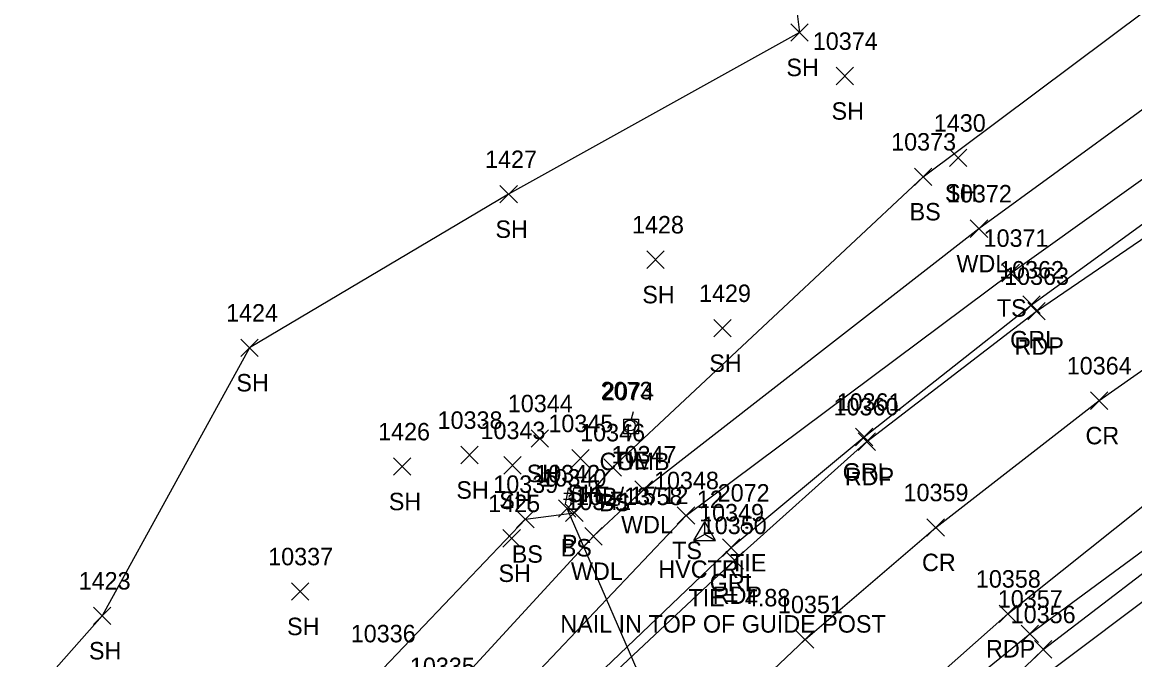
# Model space of a CAD drawing. Extents: x 1651685 to 1653558, y 889533 to 891085.
# Drawn here: x 1652813.1 to 1652940.5, y 890652 to 890725 of the extents above; entities that cross this region are included whole.
import ezdxf

# ---------------------------------------------------------------- set-up
doc = ezdxf.new("R2010")
doc.units = 0
for name, color, linetype in [('C_A', 7, 'Continuous'), ('C_C', 7, 'Continuous'), ('C_I', 7, 'Continuous'), ('CBP', 7, 'Continuous'), ('CPSM', 7, 'Continuous'), ('D_A', 7, 'Continuous'), ('D_I', 7, 'Continuous'), ('D_TIC', 7, 'Continuous'), ('DCP', 7, 'Continuous'), ('L_A', 7, 'Continuous'), ('L_I', 7, 'Continuous'), ('L_TIC', 7, 'Continuous'), ('LAWA', 7, 'Continuous'), ('LELB', 7, 'Continuous'), ('LSOGP', 7, 'Continuous'), ('P_A', 7, 'Continuous'), ('P_I', 7, 'Continuous'), ('P_TIC', 7, 'Continuous'), ('PET', 7, 'Continuous'), ('PRC', 7, 'Continuous'), ('R_A', 7, 'Continuous'), ('R_I', 7, 'Continuous'), ('R_TIC', 7, 'Continuous'), ('RGR', 7, 'Continuous'), ('U_A', 7, 'Continuous'), ('U_C', 7, 'Continuous'), ('U_I', 7, 'Continuous'), ('UP', 7, 'Continuous')]:
    doc.layers.add(name, color=color, linetype=linetype)

msp = doc.modelspace()

# ---------------------------------------------------------------- linework, layer by layer
at = {"layer": 'CBP'}
for centre, radius in [((1652882.68, 890678.86), 0.625), ((1652882.68, 890678.86), 0.0833), ((1652896.09, 890667.15), 0.625), ((1652896.09, 890667.15), 0.0833)]:
    msp.add_circle(centre, radius, dxfattribs=at)
at = {"layer": 'CPSM'}
for p, q in [((1652890.01, 890665.68), (1652891.26, 890667.85)), ((1652892.51, 890665.68), (1652891.26, 890667.85)), ((1652891.26, 890666.41), (1652891.26, 890667.85)), ((1652890.01, 890665.68), (1652891.26, 890666.41)), ((1652891.26, 890666.41), (1652891.26, 890666.41)), ((1652891.26, 890666.41), (1652892.51, 890665.68)), ((1652890.01, 890665.68), (1652892.51, 890665.68))]:
    msp.add_line(p, q, dxfattribs=at)
at = {"layer": 'D_TIC'}
for points in [[(1652874.51, 890668.35), (1652876.51, 890670.35)], [(1652876.51, 890668.35), (1652874.51, 890670.35)]]:
    msp.add_lwpolyline(points, dxfattribs=at)
at = {"layer": 'DCP'}
msp.add_lwpolyline([(1652896.07, 890622.05), (1652875.51, 890669.35)], dxfattribs=at)
at = {"layer": 'L_TIC'}
for points in [[(1652901.13, 890722.86), (1652903.13, 890724.86)], [(1652903.13, 890722.86), (1652901.13, 890724.86)], [(1652906.32, 890717.87), (1652908.32, 890719.87)], [(1652908.32, 890717.87), (1652906.32, 890719.87)], [(1652919.3, 890708.5), (1652921.3, 890710.5)], [(1652921.3, 890708.5), (1652919.3, 890710.5)], [(1652915.29, 890706.34), (1652917.29, 890708.34)], [(1652917.29, 890706.34), (1652915.29, 890708.34)], [(1652867.79, 890704.34), (1652869.79, 890706.34)], [(1652869.79, 890704.34), (1652867.79, 890706.34)], [(1652921.69, 890700.4), (1652923.69, 890702.4)], [(1652923.69, 890700.4), (1652921.69, 890702.4)], [(1652884.63, 890696.85), (1652886.63, 890698.85)], [(1652886.63, 890696.85), (1652884.63, 890698.85)], [(1652925.33, 890695.32), (1652927.33, 890697.32)], [(1652927.33, 890695.32), (1652925.33, 890697.32)], [(1652892.31, 890689), (1652894.31, 890691)], [(1652894.31, 890689), (1652892.31, 890691)], [(1652838.1, 890686.76), (1652840.1, 890688.76)], [(1652840.1, 890686.76), (1652838.1, 890688.76)], [(1652871.37, 890676.38), (1652873.37, 890678.38)], [(1652873.37, 890676.38), (1652871.37, 890678.38)], [(1652863.32, 890674.48), (1652865.32, 890676.48)], [(1652865.32, 890674.48), (1652863.32, 890676.48)], [(1652855.58, 890673.16), (1652857.58, 890675.16)], [(1652857.58, 890673.16), (1652855.58, 890675.16)], [(1652868.24, 890673.3), (1652870.24, 890675.3)], [(1652870.24, 890673.3), (1652868.24, 890675.3)], [(1652876.02, 890674.1), (1652878.02, 890676.1)], [(1652878.02, 890674.1), (1652876.02, 890676.1)], [(1652879.71, 890673.05), (1652881.71, 890675.05)], [(1652881.71, 890673.05), (1652879.71, 890675.05)], [(1652883.26, 890670.52), (1652885.26, 890672.52)], [(1652885.26, 890670.52), (1652883.26, 890672.52)], [(1652869.71, 890667.15), (1652871.71, 890669.15)], [(1652871.71, 890667.15), (1652869.71, 890669.15)], [(1652875.32, 890667.87), (1652877.32, 890669.87)], [(1652877.32, 890667.87), (1652875.32, 890669.87)], [(1652888.12, 890667.57), (1652890.12, 890669.57)], [(1652890.12, 890667.57), (1652888.12, 890669.57)], [(1652868.14, 890664.95), (1652870.14, 890666.95)], [(1652870.14, 890664.95), (1652868.14, 890666.95)], [(1652877.51, 890665.18), (1652879.51, 890667.18)], [(1652879.51, 890665.18), (1652877.51, 890667.18)], [(1652843.91, 890658.86), (1652845.91, 890660.86)], [(1652845.91, 890658.86), (1652843.91, 890660.86)], [(1652821.21, 890656.08), (1652823.21, 890658.08)], [(1652823.21, 890656.08), (1652821.21, 890658.08)], [(1652927.52, 890654.01), (1652929.52, 890656.01)], [(1652929.52, 890654.01), (1652927.52, 890656.01)], [(1652929.05, 890652.23), (1652931.05, 890654.23)], [(1652931.05, 890652.23), (1652929.05, 890654.23)]]:
    msp.add_lwpolyline(points, dxfattribs=at)
at = {"layer": 'LAWA'}
msp.add_lwpolyline([(1652817.98, 890613.54), (1652840.14, 890627.46), (1652861.15, 890647.29), (1652878.51, 890666.18), (1652884.26, 890671.52), (1652922.69, 890701.4), (1652959.19, 890728.02), (1652986.15, 890746.08), (1653025.9, 890769.89), (1653049.43, 890788.17), (1653075.47, 890803.38), (1653097.52, 890818.66), (1653132.33, 890844.48)], dxfattribs=at)
at = {"layer": 'LELB'}
for points in [[(1652773.03, 890464.56), (1652787.9, 890509.35), (1652802.92, 890548.75), (1652814.17, 890571.87), (1652832.16, 890602.17), (1652848.73, 890624.66), (1652866.01, 890644.23), (1652889.12, 890668.57), (1652926.33, 890696.32), (1652964.24, 890723.35), (1652991.22, 890740.2), (1653028.13, 890766.86), (1653057.75, 890784.91), (1653079.01, 890799.53), (1653102.53, 890813.78), (1653139.28, 890840.79)], [(1652801.17, 890441.9), (1652819.95, 890497.78), (1652834.5, 890541.46), (1652846.59, 890562.12), (1652860.39, 890582.03), (1652876.07, 890602.68), (1652893.78, 890623.65), (1652912.56, 890642.08), (1652928.52, 890655.01), (1652947.04, 890668.65), (1652977.97, 890691.06), (1653009.95, 890711.96), (1653047.06, 890737.13), (1653086.67, 890762.46), (1653129.22, 890790.4), (1653161.56, 890810.77), (1653178.09, 890819.36), (1653180.64, 890814.31), (1653173.84, 890802.86)], [(1652803.19, 890441), (1652820.95, 890497.33), (1652835.58, 890541.15), (1652847.79, 890560.97), (1652861.63, 890580.86), (1652877.83, 890601.57), (1652890.21, 890617.22), (1652895.56, 890622.27), (1652897.12, 890622.95), (1652897.22, 890624.03), (1652915.57, 890639.3), (1652930.05, 890653.23), (1652948.11, 890667.03), (1652978.83, 890689.41), (1653011.67, 890709.88), (1653048.76, 890734.73), (1653087.02, 890761.14), (1653131.31, 890788.11), (1653159.98, 890805.73), (1653164.16, 890807.03), (1653164.17, 890807.66), (1653169.82, 890813.7), (1653178.09, 890819.36)], [(1652803.19, 890441), (1652822.35, 890480.19), (1652822.96, 890495.87), (1652838.19, 890539.83), (1652849.62, 890560.27), (1652863.19, 890579.04), (1652878.87, 890600.11), (1652891.82, 890615.8), (1652896.5, 890621.01), (1652897.47, 890622.7), (1652898.8, 890623.23), (1652915.57, 890639.3), (1652950.1, 890665.22), (1652980.52, 890686.66), (1653013.67, 890707.26), (1653050.87, 890733.01), (1653089.27, 890757.95), (1653133.42, 890785.98), (1653160.95, 890802.08), (1653164.63, 890804.85), (1653167.22, 890806.35), (1653170.81, 890811.17), (1653178.09, 890819.36)], [(1652740.63, 890407.57), (1652746.83, 890413.23), (1652755.32, 890445.88), (1652760.35, 890468.2), (1652780.77, 890512.23), (1652796.45, 890551.5), (1652807.59, 890577.74), (1652825.47, 890605.79), (1652840.14, 890627.46), (1652854.42, 890651.04), (1652870.71, 890668.15), (1652876.32, 890668.87), (1652880.71, 890674.05), (1652916.29, 890707.34), (1652954.78, 890736.09), (1652983.82, 890751.78), (1653022.66, 890774.83), (1653049.43, 890788.17)]]:
    msp.add_lwpolyline(points, dxfattribs=at)
at = {"layer": 'LSOGP'}
msp.add_lwpolyline([(1653191.35, 890868.11), (1653139.25, 890847.21), (1653133.81, 890854.84), (1653132.26, 890853.62), (1653128.23, 890850.65), (1653088.88, 890824.36), (1653067.93, 890808.39), (1653036.42, 890796.38), (1653023.39, 890789.29), (1652975.72, 890758.11), (1652938.51, 890752.73), (1652900.6, 890736.09), (1652902.13, 890723.86), (1652868.79, 890705.34), (1652839.11, 890687.76), (1652822.21, 890657.08), (1652787.43, 890617.81), (1652783.5, 890592.65), (1652777.63, 890568.95), (1652768.73, 890549.07), (1652760.18, 890544.48), (1652755.23, 890514.52), (1652738.16, 890487.37)], dxfattribs=at)
at = {"layer": 'P_TIC'}
for points in [[(1652928.28, 890690.96), (1652930.28, 890692.96)], [(1652930.28, 890690.96), (1652928.28, 890692.96)], [(1652935.47, 890680.71), (1652937.47, 890682.71)], [(1652937.47, 890680.71), (1652935.47, 890682.71)], [(1652908.83, 890676.02), (1652910.83, 890678.02)], [(1652910.83, 890676.02), (1652908.83, 890678.02)], [(1652916.73, 890666.19), (1652918.73, 890668.19)], [(1652918.73, 890666.19), (1652916.73, 890668.19)], [(1652893.69, 890662.43), (1652895.69, 890664.43)], [(1652895.69, 890662.43), (1652893.69, 890664.43)], [(1652925.01, 890656.3), (1652927.01, 890658.3)], [(1652927.01, 890656.3), (1652925.01, 890658.3)], [(1652901.76, 890653.37), (1652903.76, 890655.37)], [(1652903.76, 890653.37), (1652901.76, 890655.37)]]:
    msp.add_lwpolyline(points, dxfattribs=at)
at = {"layer": 'PET'}
for points in [[(1652776.68, 890458.63), (1652791.9, 890507.53), (1652801.72, 890533.82), (1652810.09, 890553.36), (1652823.07, 890577.38), (1652836.65, 890598.71), (1652853.5, 890620.62), (1652874.5, 890644.55), (1652894.69, 890663.43), (1652909.83, 890677.02), (1652929.28, 890691.96), (1652967.44, 890717.98), (1652993.7, 890736.14), (1653032.31, 890761.89), (1653070.4, 890786.93), (1653112.15, 890813.99), (1653148.48, 890837.47), (1653192.87, 890865.71), (1653235.94, 890893.09), (1653280.18, 890921.16), (1653320.29, 890946.68)], [(1652797.7, 890444.76), (1652815.98, 890499.36), (1652826.44, 890526.94), (1652833.17, 890541.97), (1652844.38, 890563.93), (1652857.27, 890583.87), (1652872.84, 890604.95), (1652891.59, 890626.08), (1652910.84, 890643.86), (1652926.01, 890657.3), (1652944.49, 890672.05), (1652975.79, 890694.46), (1653007.52, 890715.91), (1653044.82, 890740.95), (1653083.79, 890766.34), (1653126.92, 890794.39), (1653162.42, 890817.19), (1653177.23, 890826.53), (1653212.82, 890849.27), (1653251.6, 890873.99), (1653294.22, 890900.69), (1653334.65, 890925.85)]]:
    msp.add_lwpolyline(points, dxfattribs=at)
at = {"layer": 'PRC'}
msp.add_lwpolyline([(1652786.21, 890448.94), (1652804.54, 890503.78), (1652815.08, 890532.72), (1652822.08, 890547.99), (1652834.04, 890571.05), (1652846.73, 890591.11), (1652862.72, 890612.73), (1652882.99, 890635.62), (1652902.76, 890654.37), (1652917.73, 890667.19), (1652936.47, 890681.71), (1652967.99, 890703.84), (1653000.43, 890726.04), (1653038.85, 890751.54), (1653077.14, 890776.73), (1653119.4, 890804.03), (1653156.21, 890827.39), (1653198.86, 890855.33), (1653243.54, 890883.44), (1653287.35, 890911.24), (1653327.74, 890936.2)], dxfattribs=at)
at = {"layer": 'R_TIC'}
for points in [[(1652927.71, 890691.69), (1652929.71, 890693.69)], [(1652929.71, 890691.69), (1652927.71, 890693.69)], [(1652908.53, 890676.55), (1652910.53, 890678.55)], [(1652910.53, 890676.55), (1652908.53, 890678.55)], [(1652893.3, 890663.88), (1652895.3, 890665.88)], [(1652895.3, 890663.88), (1652893.3, 890665.88)]]:
    msp.add_lwpolyline(points, dxfattribs=at)
at = {"layer": 'RGR'}
msp.add_lwpolyline([(1652753.62, 890407.5), (1652763.75, 890431.04), (1652774.48, 890459.79), (1652790.93, 890508.17), (1652800.51, 890534.29), (1652809.1, 890554.07), (1652821.88, 890578.18), (1652835.53, 890599.08), (1652852.44, 890621.25), (1652873.86, 890645.38), (1652894.3, 890664.88), (1652909.53, 890677.55), (1652928.71, 890692.69), (1652967.13, 890720.62), (1652991.99, 890738.03), (1653030.5, 890764.27), (1653069.01, 890789.08), (1653110.73, 890816.31), (1653147.12, 890839.54), (1653191.34, 890868.1), (1653234.07, 890895.44), (1653279.07, 890923.79), (1653318.83, 890948.74)], dxfattribs=at)
at = {"layer": 'UP'}
for p, q in [((1652883.08, 890680.42), (1652882.83, 890679.58)), ((1652881.99, 890677.92), (1652881.99, 890679.58)), ((1652881.99, 890679.58), (1652883.66, 890679.58)), ((1652883.66, 890679.58), (1652883.66, 890677.92)), ((1652883.66, 890677.92), (1652881.99, 890677.92)), ((1652882.58, 890677.08), (1652882.83, 890677.92)), ((1652882.83, 890678.75), (1652882.83, 890678.75))]:
    msp.add_line(p, q, dxfattribs=at)
msp.add_circle((1652882.83, 890678.75), 0.833, dxfattribs=at)

# ---------------------------------------------------------------- texts
at = {"layer": 'C_A'}
for s, p in [('TIE', (1652880.76, 890673.86)), ('TIE', (1652894.17, 890662.15)), ('HVCTRL', (1652885.95, 890661.41))]:
    msp.add_text(s, height=2, dxfattribs=at).set_placement(p)
at = {"layer": 'C_C'}
for s, p in [('TIE= 15.12', (1652876.23, 890669.86)), ('TIE= 4.88', (1652889.4, 890658.15)), ('NAIL IN TOP OF GUIDE POST', (1652874.71, 890655.15))]:
    msp.add_text(s, height=2, dxfattribs=at).set_placement(p)
at = {"layer": 'C_I'}
for s, p in [('2073', (1652879.34, 890681.86)), ('12', (1652890.36, 890669.41)), ('2072', (1652892.75, 890670.15))]:
    msp.add_text(s, height=2, dxfattribs=at).set_placement(p)
at = {"layer": 'D_A'}
msp.add_text('P', height=2, dxfattribs=at).set_placement((1652874.89, 890664.35))
at = {"layer": 'D_I'}
msp.add_text('10342', height=2, dxfattribs=at).set_placement((1652871.84, 890672.35))
at = {"layer": 'L_A'}
for s, p in [('SH', (1652900.62, 890718.86)), ('SH', (1652905.8, 890713.87)), ('SH', (1652918.79, 890704.5)), ('BS', (1652914.74, 890702.34)), ('SH', (1652867.28, 890700.34)), ('WDL', (1652920.11, 890696.4)), ('SH', (1652884.11, 890692.85)), ('TS', (1652924.74, 890691.32)), ('SH', (1652891.79, 890685)), ('SH', (1652837.59, 890682.76)), ('SH', (1652870.86, 890672.38)), ('SH', (1652862.8, 890670.48)), ('SH', (1652867.72, 890669.3)), ('SH', (1652875.51, 890670.1)), ('SH', (1652855.06, 890669.16)), ('BS', (1652879.15, 890669.05)), ('WDL', (1652881.68, 890666.52)), ('BS', (1652869.15, 890663.15)), ('BS', (1652874.76, 890663.87)), ('TS', (1652887.53, 890663.57)), ('SH', (1652867.63, 890660.95)), ('WDL', (1652875.93, 890661.18)), ('SH', (1652843.4, 890654.86)), ('SH', (1652820.7, 890652.08))]:
    msp.add_text(s, height=2, dxfattribs=at).set_placement(p)
at = {"layer": 'L_I'}
for s, p in [('10374', (1652903.65, 890721.87)), ('1430', (1652917.52, 890712.5)), ('10373', (1652912.63, 890710.34)), ('1427', (1652866.09, 890708.34)), ('10372', (1652919.02, 890704.4)), ('1428', (1652882.93, 890700.85)), ('10371', (1652923.22, 890699.32)), ('1429', (1652890.61, 890693)), ('1424', (1652836.41, 890690.76)), ('10344', (1652868.7, 890680.38)), ('10338', (1652860.65, 890678.48)), ('1426', (1652853.83, 890677.16)), ('10343', (1652865.57, 890677.3)), ('10345', (1652873.35, 890678.1)), ('10346', (1652876.99, 890677.05)), ('10347', (1652880.59, 890674.52)), ('10340', (1652872.56, 890671.87)), ('10339', (1652867.03, 890671.15)), ('10348', (1652885.45, 890671.57)), ('1425', (1652866.45, 890668.95)), ('10341', (1652875.41, 890669.18)), ('10337', (1652841.24, 890662.86)), ('1423', (1652819.52, 890660.08)), ('10357', (1652924.85, 890658.01)), ('10356', (1652926.33, 890656.23)), ('10336', (1652850.7, 890654.04)), ('10335', (1652857.48, 890650.29))]:
    msp.add_text(s, height=2, dxfattribs=at).set_placement(p)
at = {"layer": 'P_A'}
for s, p in [('RDP', (1652926.77, 890686.96)), ('CR', (1652934.9, 890676.71)), ('RDP', (1652907.32, 890672.02)), ('CR', (1652916.16, 890662.19)), ('RDP', (1652892.18, 890658.43)), ('RDP', (1652923.5, 890652.3))]:
    msp.add_text(s, height=2, dxfattribs=at).set_placement(p)
at = {"layer": 'P_I'}
for s, p in [('10363', (1652925.57, 890694.96)), ('10364', (1652932.75, 890684.71)), ('10360', (1652906.03, 890680.02)), ('10359', (1652914.05, 890670.19)), ('10350', (1652890.93, 890666.43)), ('10358', (1652922.34, 890660.3)), ('10351', (1652899.66, 890657.37))]:
    msp.add_text(s, height=2, dxfattribs=at).set_placement(p)
at = {"layer": 'R_A'}
for p in [(1652926.26, 890687.69), (1652907.07, 890672.55), (1652891.84, 890659.88)]:
    msp.add_text('GRL', height=2, dxfattribs=at).set_placement(p)
at = {"layer": 'R_I'}
for s, p in [('10362', (1652925, 890695.69)), ('10361', (1652906.38, 890680.55)), ('10349', (1652890.62, 890667.88))]:
    msp.add_text(s, height=2, dxfattribs=at).set_placement(p)
at = {"layer": 'U_A'}
msp.add_text('COMB', height=2, dxfattribs=at).set_placement((1652879.21, 890673.75))
at = {"layer": 'U_C'}
msp.add_text('#10B/13/58', height=2, dxfattribs=at).set_placement((1652875.03, 890669.75))
at = {"layer": 'U_I'}
msp.add_text('2074', height=2, dxfattribs=at).set_placement((1652879.49, 890681.75))

doc.saveas('drawing.dxf')
